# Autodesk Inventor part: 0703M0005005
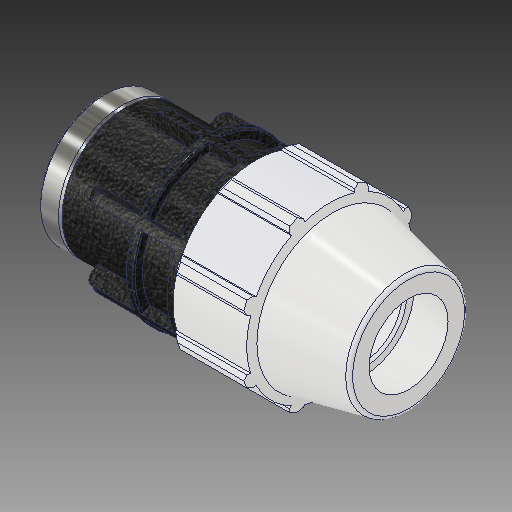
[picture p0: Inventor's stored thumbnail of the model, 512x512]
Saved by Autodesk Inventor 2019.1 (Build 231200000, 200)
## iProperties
Created: 2017-02
Part Number: 0703M0005005
Material: PVC-Piping
Description: PLASSON FEMALE ADAPTOR 1/2'' - 1/2''F
Document SubType Name: Modeling
Designer: KIM
Mass: 92.6774 g
Surface Area: 199.44 cm^2
Volume: 66.1981 cm^3
Density: 1.4 g/cm^3
Appearance: PTFE
Author: KIM
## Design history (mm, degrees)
derived "0703M0.ipt"
feature "Solid1::0703M0.ipt"
tag "TaggingFeature1"
body "Solid1"
other parameters: "d2" = 21.2, "d4" = 11.72029, "d5" = 20.5105, "d7" = 48.006, "d9" = 11.72029, "d11" = 2.34406, "d12" = 38.4048, "d13" = 120 deg, "d14" = 31.8, "d15" = 12 deg, "d16" = 43.2054, "d18" = 1.06, "d19" = 35 deg, "d20" = 17.5 deg, "d21" = 44.64558, "d23" = 0, "d25" = 360 deg, "d27" = 0.96012, "d34" = 2.4003, "d35" = 24.6126, "d36" = 0, "d42" = 20.5105, "d43" = 1.44018, "d46" = 0.636, "d49" = 58.928, "d51" = 82.042, "d53" = 0.424, "d55" = 360 deg, "d61" = 19.05, "d62" = 16.96, "d63" = 18.631, "d64" = 27.34733, "d65" = 2.4003, "d66" = 0.5, "d67" = 1, "d68" = 5.715, "d69" = 34.56432, "d70" = 1.20015, "d_" = 21.2, "E_" = 48.006, "H_" = 82.042, "l_" = 58.928, "l_2" = 19.05, "Rp_" = 18.631
